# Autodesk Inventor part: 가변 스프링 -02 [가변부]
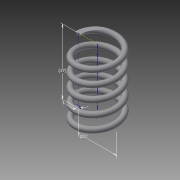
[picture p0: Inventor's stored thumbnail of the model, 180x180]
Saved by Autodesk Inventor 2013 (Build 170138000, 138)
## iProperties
Created: 2014-12
Part Number: 가변 스프링 -02 [가변부]
Material: Generic
Document SubType Name: Modeling
Designer: Administrator
Density: 1 g/cm^3
Mass: 2.40348 g
Surface Area: 32.5169 cm^2
Volume: 2.40348 cm^3
Author: Administrator
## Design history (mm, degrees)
sketch "Sketch1"
  geometry: L1 (0, 0)-(11, 0); L2 (11, 0)-(11, 36.261); L3 (11, 36.261)-(0, 36.261); L4 (0, 36.261)-(0, 0); C1 r 1.5 at (11, 0)
  constraints: 8 end point, 2 parallel, 1 centre point, 1 coincident, 1 horizontal, 1 perpendicular
  dimensions: "d0" = 3 diameter of C1; "d1" = 22 diameter of L2 L4; "d2" = 36.2612 distance between parallel lines of L1 L3 (derived)
coil "Coil1" pitch "d3" = 10; turns "d5" = 5; dims "d4" = 36.2612 (= d2), "d6" = 0, angle "d7" = 90 deg, angle "d8" = 90 deg, "d9" = 0, "d10" = 0
sketch "Sketch2"
  geometry: L1 (-12.5, 0)-(-9.5, 0) reference; 1 further point
  constraints: 1 horizontal alignment
extrude "Extrusion1" cut sketch "Sketch2" stored distance "d11" = 10; taper "d12" = 0 deg
workplane "Work Plane2"
sketch "Sketch3"
  geometry: L1 (1.5, 0)-(-1.5, 0) reference; 1 further point
  constraints: 1 horizontal alignment
extrude "Extrusion2" cut sketch "Sketch3" stored distance "d14" = 10; taper "d15" = 0 deg
body "Solid1"
node "Project Cut Edges1"
node "Project Cut Edges2"
other parameters: "d13" = 0
